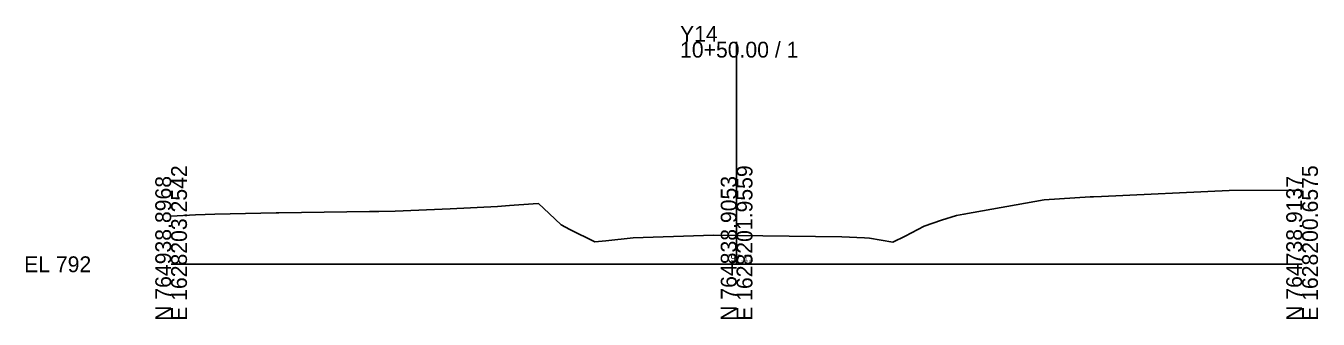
# Model space of a CAD drawing. Extents: x -26 to 1403, y -10 to 4517.
# Drawn here: x -25.7 to 202.8, y 990.3 to 1042.1 of the extents above; entities that cross this region are included whole.
import ezdxf

# ---------------------------------------------------------------- set-up
doc = ezdxf.new("R2010")
doc.units = 0
for name, color, linetype in [('Default', 7, 'Continuous'), ('Exist CMT Pavement', 7, 'Continuous'), ('Exist Cross Section Cell', 7, 'Continuous'), ('Exist XS Center Line Elevation Label', 7, 'Continuous'), ('Exist XS Ground Line', 7, 'Continuous')]:
    doc.layers.add(name, color=color, linetype=linetype)

msp = doc.modelspace()

# ---------------------------------------------------------------- linework, layer by layer
at = {"layer": 'Exist CMT Pavement'}
for points in [[(100, 1005.11), (118.63, 1004.87)], [(118.63, 1004.87), (118.63, 1004.87)]]:
    msp.add_lwpolyline(points, dxfattribs=at)
at = {"layer": 'Exist Cross Section Cell'}
for p, q in [((100, 1000), (100, 1039.32)), ((0, 1000), (100, 1000)), ((100, 1000), (200, 1000))]:
    msp.add_line(p, q, dxfattribs=at)
at = {"layer": 'Exist XS Ground Line'}
msp.add_lwpolyline([(0, 1008.48), (4.31, 1008.73), (7.7, 1008.85), (18.6, 1009.07), (19.05, 1009.11), (35.06, 1009.34), (36.73, 1009.33), (39.64, 1009.41), (49.34, 1009.82), (57.71, 1010.18), (59.86, 1010.4), (64.01, 1010.65), (64.99, 1010.71), (66.87, 1008.98), (69, 1006.99), (70.5, 1006.12), (74.93, 1003.98), (76.85, 1004.15), (81.72, 1004.69), (94.16, 1005.1), (95.97, 1005.16), (100, 1005.11), (118.63, 1004.87), (122.62, 1004.66), (123.5, 1004.59), (127.63, 1003.89), (129.78, 1004.97), (133.14, 1006.75), (136.26, 1007.79), (138.91, 1008.64), (140.21, 1008.84), (154.38, 1011.38), (162.53, 1011.93), (163.1, 1011.93), (164.51, 1012), (187.13, 1013.01), (200, 1013.11)], dxfattribs=at)

# ---------------------------------------------------------------- texts
at = {"layer": 'Default'}
msp.add_text('-', height=0.0001, dxfattribs=at).set_placement((0, 1000))
at = {"layer": 'Exist Cross Section Cell'}
for s, p in [('Y14', (90, 1039.32)), ('10+50.00 / 1', (90, 1036.52)), ('EL 792', (-26, 998.6))]:
    msp.add_text(s, height=2.8, dxfattribs=at).set_placement(p)
for s, p in [('E 1628203.2542', (2.8, 990)), ('E 1628201.9559', (102.8, 990)), ('E 1628200.6575', (202.8, 990)), ('N 764938.8968', (0, 990)), ('N 764838.9053', (100, 990)), ('N 764738.9137', (200, 990))]:
    msp.add_text(s, height=2.8, rotation=90, dxfattribs=at).set_placement(p)
at = {"layer": 'Exist XS Center Line Elevation Label'}
msp.add_text('797.11', height=1.2, dxfattribs=at).set_placement((98.05, 1000.51))

doc.saveas('drawing.dxf')
